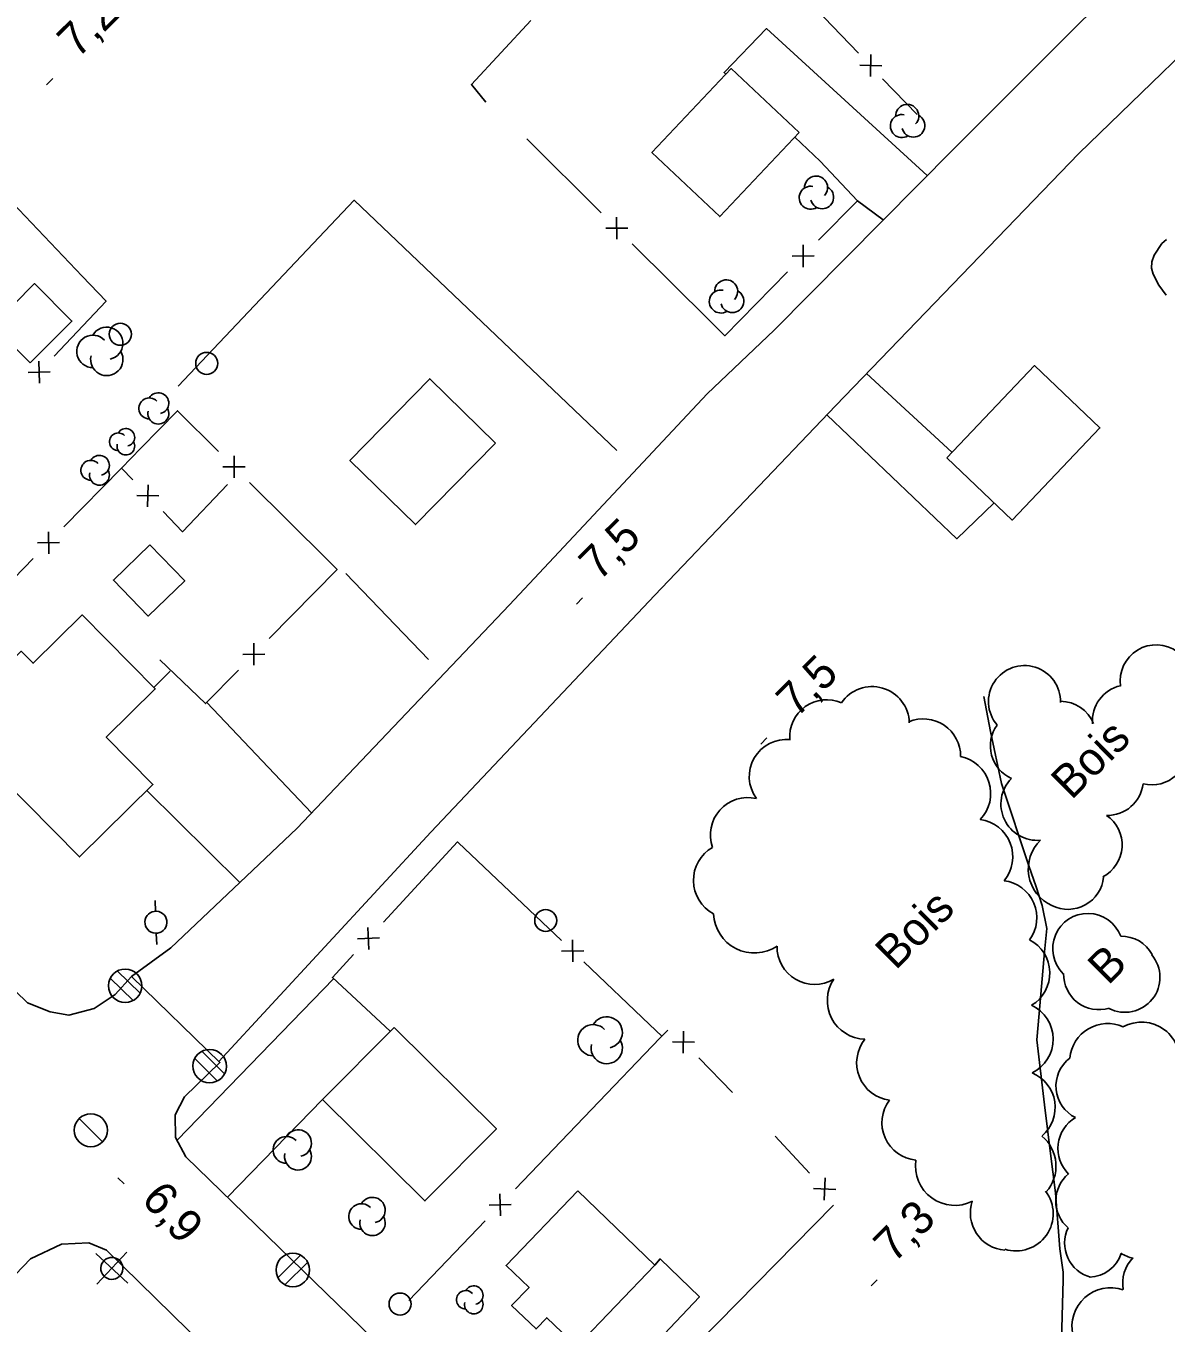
# Model space of a CAD drawing. Extents: x 381879 to 384696, y 5564785 to 5567594.
# Drawn here: x 382841.1 to 382944.6, y 5565671 to 5565788.8 of the extents above; entities that cross this region are included whole.
import ezdxf

# ---------------------------------------------------------------- set-up
doc = ezdxf.new("R2010")
doc.units = 0
for name, color, linetype in [('Niveau 19', 7, 'Continuous'), ('Niveau 2', 7, 'Continuous'), ('Niveau 21', 7, 'Continuous'), ('Niveau 22', 7, 'Continuous'), ('Niveau 3', 7, 'Continuous'), ('Niveau 31', 7, 'Continuous'), ('Niveau 36', 7, 'Continuous'), ('Niveau 37', 7, 'Continuous'), ('Niveau 41', 7, 'Continuous'), ('Niveau 44', 7, 'Continuous')]:
    doc.layers.add(name, color=color, linetype=linetype)

msp = doc.modelspace()

# ---------------------------------------------------------------- linework, layer by layer
at = {"layer": 'Niveau 19'}
for points in [[(382922.96, 5565775.21), (382908.35, 5565788.57), (382904.51, 5565784.57), (382904.67, 5565784.42)], [(382910.93, 5565778.71), (382913.23, 5565776.53)], [(382916.63, 5565772.93), (382918.96, 5565771.18)], [(382925.2, 5565750.09), (382917.44, 5565757.23)], [(382913.83, 5565753.48), (382925.64, 5565742.22), (382929.03, 5565745.47)], [(382852.74, 5565728.7), (382854.22, 5565730.2)], [(382857.53, 5565727.35), (382867.06, 5565717.31)], [(382860.53, 5565710.98), (382852.09, 5565719.36)], [(382869.08, 5565702.28), (382854.85, 5565687.57)], [(382859.42, 5565682.4), (382868.05, 5565691.28)], [(382898.23, 5565676.23), (382898.69, 5565676.8), (382902.26, 5565673.35), (382886.21, 5565656.37)]]:
    msp.add_lwpolyline(points, dxfattribs=at)
at = {"layer": 'Niveau 2'}
msp.add_lwpolyline([(382944.65, 5565764.35), (382943.99, 5565765.27), (382943.47, 5565766.26), (382943.32, 5565766.81), (382943.34, 5565767.39), (382943.56, 5565767.98), (382944.26, 5565769.03), (382944.69, 5565769.41)], dxfattribs=at)
at = {"layer": 'Niveau 21'}
for points in [[(383064.1, 5565858.11), (383048.13, 5565853.66), (383037.45, 5565850.22), (383025.4, 5565844.77), (383013.84, 5565839.23), (383000.34, 5565832), (382984.28, 5565823), (382968.65, 5565813.92), (382957.48, 5565806.76), (382947.18, 5565799.02), (382936.93, 5565789.21), (382925.34, 5565777.61), (382909.05, 5565761.18), (382902.96, 5565755.38)], [(382914.61, 5565754.3), (382936.73, 5565777.21), (382952.8, 5565792.82), (382963.76, 5565801.52), (382976.97, 5565810.61), (383000.04, 5565824), (383016.43, 5565833.11), (383031.77, 5565840.06), (383045.77, 5565844.63), (383055.95, 5565847.35), (383061.35, 5565847.84), (383065.37, 5565846.21), (383068.45, 5565843.53), (383070.89, 5565839.89)], [(382841.27, 5565700.06), (382759.89, 5565779.18)], [(382902.96, 5565755.38), (382885.01, 5565736.22), (382865.72, 5565715.9), (382854.28, 5565705.05), (382850.69, 5565702.45)], [(382858.63, 5565694.73), (382877.87, 5565715.55), (382898.21, 5565737.09), (382914.61, 5565754.3)], [(382855.64, 5565686.08), (382855.64, 5565686.08), (382854.71, 5565687.82), (382854.66, 5565689.89), (382855.52, 5565691.52), (382858.73, 5565694.63), (382850.69, 5565702.45), (382849.23, 5565700.83), (382847.3, 5565699.55), (382845, 5565698.95), (382843.32, 5565699.25), (382841.27, 5565700.06)], [(382961.8, 5565583.5), (382885.34, 5565657.21), (382855.64, 5565686.08)], [(382836.74, 5565671.85), (382841.52, 5565676.79), (382844.35, 5565678.14), (382846.84, 5565678.25), (382848.42, 5565677.6)], [(382848.42, 5565677.6), (382879.6, 5565647.04)]]:
    msp.add_lwpolyline(points, dxfattribs=at)
at = {"layer": 'Niveau 22'}
for points in [[(382929.7, 5565720), (382928.7, 5565724.7), (382928.1, 5565727.9)], [(382932.2, 5565712.4), (382929.7, 5565720)], [(382933.6, 5565704.7), (382933.8, 5565706.8), (382933.4, 5565708.9), (382932.8, 5565710.7), (382932.2, 5565712.4)], [(382932.9, 5565696.7), (382933.1, 5565699.1), (382933.6, 5565704.7)], [(382933.6, 5565690.8), (382932.9, 5565696.7)], [(382934.6, 5565682.8), (382934.1, 5565686.6), (382933.6, 5565690.8)], [(382935.3, 5565674.9), (382935.3, 5565675.6), (382935, 5565677.7), (382934.6, 5565682.8)], [(382935, 5565666.9), (382935.1, 5565668.3), (382935.3, 5565674.9)]]:
    msp.add_lwpolyline(points, dxfattribs=at)
at = {"layer": 'Niveau 3'}
for p, q in [((382842.99, 5565783.47), (382843.56, 5565784.04)), ((382891.1, 5565736.28), (382891.65, 5565736.86)), ((382907.83, 5565723.55), (382908.4, 5565724.12)), ((382849.47, 5565684.17), (382850.04, 5565683.62)), ((382917.85, 5565674.34), (382918.42, 5565674.91))]:
    msp.add_line(p, q, dxfattribs=at)
at = {"layer": 'Niveau 31'}
for points in [[(382911.31, 5565779.11), (382904.11, 5565771.49), (382897.95, 5565777.31), (382905.15, 5565784.93)], [(382841.5, 5565758.2), (382838.1, 5565761.6), (382841.9, 5565765.4), (382845.3, 5565762)], [(382924.72, 5565749.58), (382932.7, 5565757.95), (382938.63, 5565752.29), (382930.65, 5565743.92)], [(382883.75, 5565750.91), (382876.5, 5565743.5), (382870.53, 5565749.34), (382877.78, 5565756.75)], [(382852.37, 5565741.67), (382855.54, 5565738.41), (382852.23, 5565735.2), (382849.06, 5565738.46)], [(382834.02, 5565725.41), (382840.69, 5565732), (382841.77, 5565730.91), (382846.21, 5565735.3), (382852.86, 5565728.58), (382848.41, 5565724.18), (382852.64, 5565719.9), (382845.98, 5565713.32)], [(382874.55, 5565697.83), (382883.83, 5565688.61), (382877.34, 5565682.07), (382868.05, 5565691.28)], [(382891.22, 5565682.97), (382898.23, 5565676.23), (382891.13, 5565668.84), (382888.41, 5565671.45), (382887.43, 5565670.43), (382885.22, 5565672.56), (382886.8, 5565674.2), (382884.71, 5565676.21)]]:
    msp.add_lwpolyline(points, close=True, dxfattribs=at)
at = {"layer": 'Niveau 36'}
for p, q in [((382852.84, 5565709.37), (382852.89, 5565708.37)), ((382852.99, 5565705.37), (382852.95, 5565706.37)), ((382848.78, 5565702.3), (382850.85, 5565700.27)), ((382851.48, 5565700.94), (382849.41, 5565702.97)), ((382856.46, 5565695), (382858.5, 5565692.94)), ((382859.14, 5565693.6), (382857.1, 5565695.66)), ((382848.08, 5565687.42), (382845.96, 5565689.54)), ((382847.45, 5565677.3), (382850.36, 5565674.58)), ((382847.55, 5565674.49), (382850.27, 5565677.4)), ((382866.04, 5565677.13), (382863.98, 5565675.09)), ((382864.64, 5565674.45), (382866.7, 5565676.49))]:
    msp.add_line(p, q, dxfattribs=at)
for centre, radius in [((382849.69, 5565760.8), 1), ((382857.53, 5565758.15), 1), ((382888.31, 5565707.54), 1), ((382847.01, 5565688.48), 1.5), ((382865.35, 5565675.79), 1.52), ((382875.09, 5565672.7), 1)]:
    msp.add_circle(centre, radius, dxfattribs=at)
for centre, major_axis, ratio in [((382852.92, 5565707.38), (-0.05, -0.999), 0.999983), ((382850.13, 5565701.61), (0.01, 1.52), 0.999981), ((382857.8, 5565694.31), (-0.02, -1.52), 0.999984), ((382848.92, 5565675.94), (-0.048, -0.999), 0.999982)]:
    msp.add_ellipse(centre, major_axis=major_axis, ratio=ratio, dxfattribs=at)
at = {"layer": 'Niveau 37'}
for p, q in [((382917.8, 5565784.21), (382917.84, 5565786.21)), ((382916.82, 5565785.23), (382918.82, 5565785.19)), ((382895.76, 5565770.43), (382893.76, 5565770.42)), ((382894.75, 5565771.43), (382894.76, 5565769.42)), ((382911.68, 5565768.91), (382911.7, 5565766.9)), ((382910.69, 5565767.9), (382912.69, 5565767.91)), ((382841.32, 5565757.33), (382843.32, 5565757.39)), ((382842.29, 5565758.36), (382842.35, 5565756.36)), ((382860.01, 5565749.74), (382860.01, 5565747.74)), ((382861.01, 5565748.74), (382859.01, 5565748.74)), ((382852.21, 5565747.13), (382852.17, 5565745.13)), ((382853.19, 5565746.11), (382851.19, 5565746.15)), ((382843.16, 5565742.86), (382843.19, 5565740.85)), ((382842.18, 5565741.84), (382844.18, 5565741.87)), ((382861.82, 5565730.72), (382861.8, 5565732.72)), ((382862.81, 5565731.73), (382860.81, 5565731.71)), ((382872.25, 5565704.91), (382872.17, 5565706.91)), ((382873.21, 5565705.95), (382871.21, 5565705.87)), ((382890.78, 5565703.77), (382890.73, 5565705.77)), ((382889.76, 5565704.74), (382891.76, 5565704.79)), ((382900.8, 5565695.49), (382900.83, 5565697.49)), ((382899.81, 5565696.51), (382901.81, 5565696.48)), ((382914.64, 5565683.11), (382912.64, 5565683.18)), ((382913.67, 5565684.15), (382913.6, 5565682.14)), ((382884.2, 5565680.7), (382884.16, 5565682.71)), ((382885.18, 5565681.73), (382883.18, 5565681.68))]:
    msp.add_line(p, q, dxfattribs=at)
for points in [[(382912.01, 5565791.25), (382916.72, 5565786.33)], [(382882.86, 5565781.89), (382881.56, 5565783.48), (382886.96, 5565789.31)], [(382918.88, 5565784.01), (382922.04, 5565780.76)], [(382893.34, 5565771.84), (382886.6, 5565778.55)], [(382913.23, 5565776.53), (382916.63, 5565772.93), (382913.09, 5565769.33)], [(382839.32, 5565773.33), (382846.21, 5565766.08)], [(382903.26, 5565761.96), (382896.17, 5565769.01)], [(382846.21, 5565766.08), (382848.39, 5565763.79), (382843.69, 5565758.81)], [(382910.28, 5565766.48), (382904.56, 5565760.66), (382903.26, 5565761.96)], [(382858.59, 5565750.15), (382854.87, 5565753.85), (382851.55, 5565750.45)], [(382851.55, 5565750.45), (382849.79, 5565748.64), (382844.57, 5565743.29)], [(382850.81, 5565747.57), (382849.79, 5565748.64)], [(382859.41, 5565747.15), (382855.32, 5565742.86), (382853.58, 5565744.68)], [(382868.52, 5565740.28), (382861.43, 5565747.33)], [(382841.78, 5565740.42), (382834.8, 5565733.26)], [(382863.21, 5565733.15), (382869.37, 5565739.43), (382868.52, 5565740.28)], [(382853.29, 5565731.23), (382857.43, 5565727.25), (382860.41, 5565730.29)], [(382873.57, 5565707.38), (382880.31, 5565714.68), (382880.35, 5565714.64)], [(382880.35, 5565714.64), (382889.75, 5565705.71)], [(382874.2, 5565697.48), (382868.94, 5565702.37), (382870.85, 5565704.44)], [(382891.78, 5565703.77), (382897.75, 5565698.1)], [(382892.47, 5565690.38), (382898.67, 5565696.86), (382898.86, 5565697.04), (382899.41, 5565697.58)], [(382897.75, 5565698.1), (382898.86, 5565697.04)], [(382902.2, 5565695.06), (382905.27, 5565691.9)], [(382885.56, 5565683.15), (382892.47, 5565690.38)], [(382912.27, 5565684.6), (382909.14, 5565687.94)], [(382907.44, 5565674.56), (382914.45, 5565681.69)], [(382875.89, 5565673.03), (382882.8, 5565680.26)], [(382900.43, 5565667.43), (382907.44, 5565674.56)]]:
    msp.add_lwpolyline(points, dxfattribs=at)
at = {"layer": 'Niveau 41'}
for points in [[(382894.78, 5565750.24), (382870.92, 5565772.97), (382854.93, 5565756.09)], [(382870.15, 5565739.06), (382877.68, 5565731.25)]]:
    msp.add_lwpolyline(points, dxfattribs=at)
at = {"layer": 'Niveau 44'}
for centre, radius, start, end in [((382848.46, 5565759.98), 1.47, 282.2692, 149.7262), ((382847.2, 5565759.24), 1.47, 44.1153, 269.8039), ((382848.46, 5565758.51), 1.47, 166.9368, 29.6212), ((382853.14, 5565754.53), 0.949, 282.2692, 149.7262), ((382852.32, 5565754.06), 0.949, 44.1153, 269.8039), ((382853.14, 5565753.59), 0.949, 166.9368, 29.6212), ((382849.5, 5565751.03), 0.801, 44.1153, 269.8039), ((382850.19, 5565751.43), 0.801, 282.2692, 149.7262), ((382850.19, 5565750.63), 0.801, 166.9368, 29.6212), ((382847.01, 5565748.44), 0.902, 44.1153, 269.8039), ((382847.79, 5565748.89), 0.902, 282.2692, 149.7262), ((382847.79, 5565747.99), 0.902, 166.9368, 29.6212), ((382906.67, 5565715.3), 3.41, 77.1196, 199.1345), ((382937.53, 5565704.99), 3.19, 20.5118, 225.744), ((382930.99, 5565696.75), 3.4, 296.0562, 65.2525), ((382893.85, 5565697.37), 1.42, 282.2692, 149.7262), ((382892.63, 5565696.66), 1.42, 44.1153, 269.8039), ((382893.85, 5565695.95), 1.42, 166.9368, 29.6212), ((382919.95, 5565694.61), 3.41, 141.2369, 262.9374), ((382938.06, 5565686.83), 3.25, 120.4841, 225.5921), ((382864.78, 5565686.7), 1.22, 44.1153, 269.8039), ((382865.82, 5565687.31), 1.22, 282.2692, 149.7262), ((382865.82, 5565686.09), 1.22, 166.9368, 29.6212), ((382872.58, 5565681.23), 1.16, 282.2692, 149.7262), ((382871.58, 5565680.65), 1.16, 44.1153, 269.8039), ((382872.58, 5565680.07), 1.16, 166.9368, 29.6212), ((382881.05, 5565673.08), 0.842, 44.1153, 269.8039), ((382881.78, 5565673.5), 0.842, 282.2692, 149.7262), ((382881.78, 5565672.65), 0.842, 166.9368, 29.6212)]:
    msp.add_arc(centre, radius, start, end, dxfattribs=at)
for centre, major_axis, ratio, start_param, end_param in [((382921.14, 5565780.63), (0.912, -0.513), 0.999925, 6.029005, 9.968014), ((382920.65, 5565779.71), (0.912, -0.513), 0.999925, 1.88946, 5.776035), ((382921.69, 5565779.75), (0.912, -0.513), 0.999925, 3.902388, 7.872264), ((382912.86, 5565774.12), (0.912, -0.513), 0.999925, 6.029005, 9.968014), ((382912.37, 5565773.2), (0.912, -0.513), 0.999925, 1.88946, 5.776035), ((382913.41, 5565773.24), (0.912, -0.513), 0.999925, 3.902388, 7.872264), ((382904.7, 5565764.69), (0.912, -0.513), 0.999925, 6.029005, 9.968014), ((382904.21, 5565763.77), (0.912, -0.513), 0.999925, 1.88946, 5.776035), ((382905.25, 5565763.81), (0.912, -0.513), 0.999925, 3.902388, 7.872264), ((382943.74, 5565729.32), (-3.25, 0.29), 0.999932, 2.995713, 6.523443), ((382931.78, 5565727.43), (-2.96, -1.39), 0.999847, 2.679992, 6.551787), ((382917.95, 5565725.41), (0.04, 3.38), 0.999003, 4.750396, 7.267537), ((382941.22, 5565725.67), (-2.26, -2.37), 0.999847, 4.123836, 5.552982), ((382913.84, 5565724.22), (-3.05, 1.45), 0.999984, 4.754028, 6.800847), ((382935.04, 5565724.19), (1.7, 2.79), 0.998218, 5.647497, 6.827181), ((382922.6, 5565722.47), (-2.97, 1.62), 0.999937, 3.633537, 5.612075), ((382931.95, 5565723.41), (-2.97, -1.35), 0.99989, 5.23988, 7.001722), ((382910.18, 5565720.61), (-1.47, -3.05), 0.999984, 3.487675, 5.787847), ((382943.34, 5565723.13), (2.37, 2.25), 0.999932, 3.710323, 5.705773), ((382925.26, 5565719.08), (3.3, 1.01), 0.998923, 5.228092, 7.34609), ((382932.94, 5565718.12), (-3.17, -0.92), 0.999904, 5.222171, 7.665289), ((382939.31, 5565720.35), (-0.19, -3.26), 0.999697, 0.032393, 1.511326), ((382927.31, 5565713.33), (3.06, 1.5), 0.99986, 5.136142, 7.264764), ((382937.39, 5565714.39), (3.08, 1.07), 0.998526, 4.853913, 6.924551), ((382905.18, 5565711.19), (-3.45, 0.2), 0.999272, 5.291911, 7.421027), ((382935.77, 5565712.22), (-3.6, 0.56), 0.999936, 5.630895, 7.583283), ((382935.73, 5565711.81), (2.66, 1.88), 0.999932, 3.633327, 5.567711), ((382929.5, 5565707.78), (3.09, 1.43), 0.999435, 5.220108, 7.291894), ((382907.25, 5565708.28), (-1.66, -3.3), 0.99988, 5.216937, 7.344452), ((382930.67, 5565702.76), (3.41, 0.12), 0.997962, 5.216651, 7.338226), ((382940.59, 5565702.92), (-2.49, 1.99), 0.999124, 4.31772, 5.40854), ((382912.72, 5565705.13), (3.4, 0.01), 0.999995, 3.113702, 5.245758), ((382940.9, 5565702.38), (2.42, -2.07), 0.997657, 4.940661, 7.690226), ((382917.4, 5565700.27), (3.52, -0.14), 0.999984, 2.595743, 4.720821), ((382938.52, 5565702.63), (1.95, -2.52), 0.999239, 4.021434, 5.926772), ((382942.41, 5565694.84), (-3.37, 0.82), 0.999394, 3.150669, 5.459094), ((382939.34, 5565694.72), (-2.07, -2.77), 0.999104, 3.36585, 5.260847), ((382937.85, 5565692.5), (2.8, -1.57), 0.999692, 2.736054, 4.758661), ((382931.16, 5565690.56), (-2.28, 2.53), 0.999995, 3.11551, 5.147916), ((382922.25, 5565689.17), (-3.36, -0.6), 0.999927, 5.459739, 7.583479), ((382931.08, 5565685.23), (3.5, -0.67), 0.999995, 5.7523, 7.345838), ((382925.46, 5565685.23), (-2.44, -2.61), 0.999533, 5.311097, 7.499846), ((382937.83, 5565682.05), (2.16, -2.37), 0.999871, 3.096472, 4.839338), ((382930.25, 5565680.97), (-2.45, -2.34), 0.99666, 5.196684, 7.014604), ((382931.01, 5565680.9), (2.34, 2.44), 0.999984, 3.600369, 6.128438), ((382938.64, 5565678.23), (3.14, -0.69), 0.999871, 2.912207, 4.658223), ((382937.54, 5565678.33), (2.71, 1.72), 0.999871, 4.197415, 5.386715), ((382942.27, 5565680), (1.19, -2.97), 0.999821, 5.330125, 5.703199), ((382944.02, 5565674.59), (-3.28, -0.56), 0.998371, 5.349456, 6.289606), ((382939.61, 5565670.67), (-2.36, 2.61), 0.999809, 5.221186, 7.345761)]:
    msp.add_ellipse(centre, major_axis=major_axis, ratio=ratio, start_param=start_param, end_param=end_param, dxfattribs=at)

# ---------------------------------------------------------------- texts
at = {"layer": 'Niveau 3'}
for s, rotation, p in [('7,2', 44.7717, (382845.8, 5565785.79)), ('7,5  ', 44.7717, (382893.16, 5565738.29)), ('7,5', 44.7717, (382911.08, 5565725.87)), ('6,9  ', 311.7808, (382851.5, 5565682.14)), ('7,3  ', 44.7717, (382919.92, 5565676.34))]:
    msp.add_text(s, height=3, rotation=rotation, dxfattribs=at).set_placement(p)
at = {"layer": 'Niveau 44'}
for s, p in [('Bois', (382936.04, 5565718.42)), ('Bois', (382920.07, 5565702.96)), ('B', (382939.37, 5565701.58))]:
    msp.add_text(s, height=3, rotation=44.7707, dxfattribs=at).set_placement(p)

doc.saveas('drawing.dxf')
